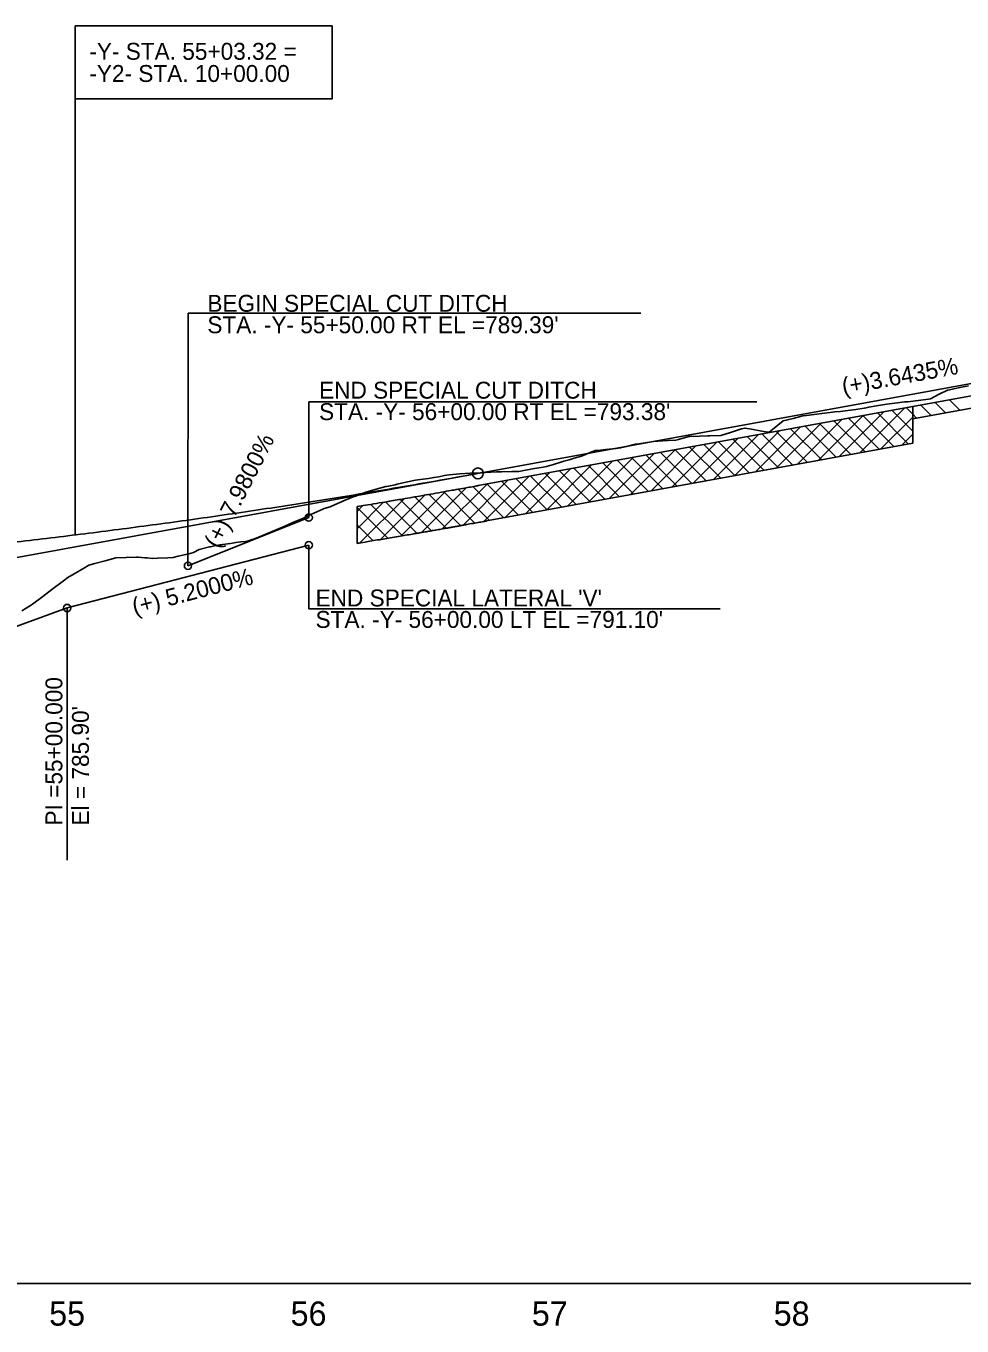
# Model space of a CAD drawing. Extents: x 579185 to 595036, y -53221 to -44640.
# Drawn here: x 583809 to 584197, y -47238 to -46700 of the extents above; entities that cross this region are included whole.
import ezdxf

# ---------------------------------------------------------------- set-up
doc = ezdxf.new("R2010")
doc.units = 0
for name, color, linetype in [('Exist Profile Cell', 7, 'Continuous'), ('Exist Vertical Profile Ground Line', 7, 'Continuous'), ('Exist Vertical Profile Horizontal Axis Label Major', 7, 'Continuous'), ('Prop Grid Mask', 7, 'Continuous'), ('Prop Hatching', 7, 'Continuous'), ('Prop Vertical Profile Curve Label', 7, 'Continuous'), ('Prop Vertical Profile Ditch Grade Left', 7, 'Continuous'), ('Prop Vertical Profile Ditch Grade Left Label', 7, 'Continuous'), ('Prop Vertical Profile Ditch Grade Right', 7, 'Continuous'), ('Prop Vertical Profile Ditch Grade Right Label', 7, 'Continuous'), ('Prop Vertical Profile Grade', 7, 'Continuous'), ('Prop Vertical Profile Grade Label', 7, 'Continuous'), ('Prop VPI Ditch Grade Left Label', 7, 'Continuous'), ('Prop VPI Ditch Grade Right Label', 7, 'Continuous'), ('Prop VPI Label', 7, 'Continuous'), ('Scratch_Level_1', 7, 'Continuous')]:
    doc.layers.add(name, color=color, linetype=linetype)

msp = doc.modelspace()

# ---------------------------------------------------------------- linework, layer by layer
at = {"layer": 'Exist Profile Cell'}
msp.add_line((579326.24, -47220.55), (584953.7, -47220.55), dxfattribs=at)
at = {"layer": 'Exist Vertical Profile Ground Line'}
for points in [[(584013.14, -46884.53), (584014.6, -46884.24), (584018.23, -46883.53), (584018.92, -46883.42), (584023.23, -46882.75), (584024.62, -46882.53), (584027.55, -46881.64), (584031.04, -46880.57), (584031.86, -46880.33), (584034.11, -46879.67), (584036.18, -46879.08), (584039.15, -46878.24), (584040.49, -46877.63), (584041.13, -46877.33), (584044.8, -46875.81), (584046.96, -46875.75), (584049.12, -46875.51), (584053.43, -46875.04), (584055.34, -46874.83), (584057.75, -46874.23), (584061.51, -46873.31), (584062.06, -46873.22), (584066.38, -46872.56), (584069.9, -46872.02), (584070.69, -46871.97), (584075, -46871.72), (584078.25, -46871.53), (584079.32, -46871.25), (584083.63, -46870.11), (584084, -46870.01), (584087.95, -46869.89), (584091.38, -46869.79), (584092.26, -46869.78), (584096.84, -46869.7), (584100.89, -46868.41), (584105.42, -46866.97), (584106.85, -46866.56), (584109.52, -46867.03), (584113.83, -46867.81), (584116.48, -46868.28), (584116.85, -46868.3), (584117.53, -46867.72), (584118.15, -46867.23), (584122.63, -46863.66), (584126.78, -46862.61), (584129.78, -46861.85), (584130.75, -46861.51), (584131.09, -46861.48), (584132.25, -46861.38), (584135.4, -46860.97), (584139.72, -46860.41), (584142.15, -46860.09), (584144.03, -46859.92), (584146.31, -46859.71), (584148.35, -46859.43), (584152.66, -46858.85), (584156.22, -46858.37), (584156.98, -46858.17), (584158.04, -46857.89), (584161.29, -46857.38), (584165.6, -46856.7), (584166.67, -46856.54), (584169.92, -46856.1), (584172.87, -46855.71), (584174.28, -46855.7), (584178.55, -46855.14), (584182.86, -46854.58), (584183.66, -46854.48), (584185.37, -46853.51), (584187.18, -46852.61), (584190.66, -46850.88), (584191.49, -46850.71), (584195.81, -46849.81), (584199.31, -46849.08)], [(583807.52, -46942.19), (583811, -46940.07), (583811.83, -46939.46), (583816.15, -46936.24), (583819.88, -46933.45), (583820.46, -46933.03), (583823.68, -46930.68), (583824.77, -46929.83), (583826.53, -46928.46), (583829.09, -46926.96), (583833.4, -46924.43), (583835.17, -46923.39), (583837.72, -46922.69), (583842.03, -46921.52), (583846.35, -46920.35), (583850.66, -46920.19), (583854.97, -46920.03), (583855.58, -46920.01), (583858.33, -46920.25), (583859.29, -46920.35), (583861.43, -46920.57), (583863.6, -46920.46), (583867.92, -46920.26), (583870.11, -46920.15), (583872.23, -46919.65), (583876.55, -46918.62), (583878.59, -46918.06), (583880.86, -46916.88), (583885.17, -46915.8), (583885.5, -46915.71), (583887.27, -46915.28), (583889.49, -46914.96), (583893.8, -46914.33), (583896.05, -46914), (583898.12, -46913.73), (583900.06, -46913.47), (583901.68, -46913.07), (583902.43, -46912.83), (583903.85, -46912.37), (583906.75, -46911.17), (583911.06, -46909.39), (583915.37, -46907.61), (583916.37, -46907.19), (583919.69, -46905.72), (583924, -46903.81), (583925.89, -46902.97), (583928.32, -46901.83), (583932.03, -46900.09), (583932.63, -46899.9), (583935.04, -46899.12), (583936.95, -46898.31), (583941.26, -46896.48), (583944.6, -46895.07), (583945.57, -46894.72), (583949.89, -46893.18), (583950.89, -46892.82), (583954.2, -46891.91), (583958.14, -46890.82), (583958.52, -46890.75), (583962.06, -46890.02), (583962.83, -46889.85), (583967.15, -46888.9), (583970.47, -46888.17), (583971.46, -46888.03), (583975.77, -46887.42), (583978.03, -46887.11), (583980.09, -46886.7), (583982.44, -46886.25), (583984.4, -46885.96), (583985.79, -46885.75), (583988.72, -46885.57), (583993.03, -46885.31), (583997.35, -46885.05), (584001.66, -46884.79), (584003.92, -46884.66), (584005.98, -46884.63), (584010.29, -46884.57), (584013.14, -46884.53)]]:
    msp.add_lwpolyline(points, dxfattribs=at)
at = {"layer": 'Prop Grid Mask'}
msp.add_lwpolyline([(583829.56, -46700.19), (583935.88, -46700.19), (583935.88, -46730.38), (583829.56, -46730.38)], close=True, dxfattribs=at)
at = {"layer": 'Prop Hatching'}
for p, q in [((583997.13, -46890.28), (584176.24, -46857.65)), ((584154.34, -46876.89), (584172.99, -46858.24)), ((584167.6, -46859.23), (584176.24, -46867.87)), ((584173.58, -46858.14), (584176.24, -46860.79)), ((584176.24, -46872.9), (584176.24, -46857.65)), ((584119.76, -46883.19), (584138.4, -46864.55)), ((584128.41, -46881.61), (584147.05, -46862.97)), ((584137.05, -46880.04), (584155.7, -46861.39)), ((584137.69, -46864.68), (584150.59, -46877.57)), ((584143.67, -46863.59), (584156.57, -46876.48)), ((584145.7, -46878.46), (584164.34, -46859.82)), ((584149.65, -46862.5), (584162.55, -46875.39)), ((584155.63, -46861.41), (584168.53, -46874.3)), ((584161.62, -46860.32), (584174.51, -46873.21)), ((584162.99, -46875.31), (584176.24, -46862.07)), ((584093.82, -46887.91), (584112.46, -46869.27)), ((584102.47, -46886.34), (584121.11, -46867.7)), ((584107.78, -46870.12), (584120.68, -46883.02)), ((584111.11, -46884.76), (584129.76, -46866.12)), ((584113.77, -46869.03), (584126.66, -46881.93)), ((584119.75, -46867.94), (584132.64, -46880.84)), ((584125.73, -46866.85), (584138.63, -46879.75)), ((584131.71, -46865.76), (584144.61, -46878.66)), ((584171.64, -46873.74), (584176.24, -46869.14)), ((583999.82, -46905.04), (584176.24, -46872.9)), ((584059.24, -46894.21), (584077.88, -46875.57)), ((584067.88, -46892.64), (584086.53, -46874)), ((584076.53, -46891.06), (584095.17, -46872.42)), ((584077.88, -46875.57), (584090.77, -46888.47)), ((584083.86, -46874.48), (584096.76, -46887.38)), ((584085.18, -46889.49), (584103.82, -46870.85)), ((584089.84, -46873.39), (584102.74, -46886.29)), ((584095.82, -46872.3), (584108.72, -46885.2)), ((584101.8, -46871.21), (584114.7, -46884.11)), ((584033.3, -46898.94), (584051.94, -46880.3)), ((584041.94, -46897.36), (584060.59, -46878.72)), ((584047.97, -46881.02), (584060.87, -46893.92)), ((584050.59, -46895.79), (584069.23, -46877.15)), ((584053.95, -46879.93), (584066.85, -46892.83)), ((584059.93, -46878.84), (584072.83, -46891.74)), ((584065.91, -46877.75), (584078.81, -46890.65)), ((584071.9, -46876.66), (584084.79, -46889.56)), ((584007.36, -46903.67), (584026, -46885.02)), ((584016.01, -46902.09), (584034.65, -46883.45)), ((584018.06, -46886.47), (584030.96, -46899.37)), ((584024.04, -46885.38), (584036.94, -46898.28)), ((584024.65, -46900.51), (584043.3, -46881.87)), ((584030.03, -46884.29), (584042.92, -46897.19)), ((584036.01, -46883.2), (584048.9, -46896.1)), ((584041.99, -46882.11), (584054.89, -46895.01)), ((583972.93, -46909.81), (583991.44, -46891.31)), ((583981.49, -46908.32), (584000.06, -46889.75)), ((583988.14, -46891.9), (584001.05, -46904.81)), ((583990.1, -46906.79), (584008.71, -46888.17)), ((583994.13, -46890.82), (584007.03, -46903.72)), ((583997.12, -46890.28), (583997.13, -46890.28)), ((583998.72, -46905.24), (584017.36, -46886.6)), ((584000.12, -46889.74), (584013.02, -46902.63)), ((584006.1, -46888.65), (584019, -46901.55)), ((584012.08, -46887.56), (584024.98, -46900.46)), ((583946.24, -46908.22), (583957.18, -46897.28)), ((583947.43, -46914.1), (583965.69, -46895.83)), ((583955.9, -46912.7), (583974.24, -46894.36)), ((583958.02, -46897.14), (583971.02, -46910.14)), ((583964.07, -46896.11), (583977.05, -46909.1)), ((583964.4, -46911.27), (583982.81, -46892.85)), ((583970.1, -46895.08), (583983.07, -46908.04)), ((583976.13, -46894.03), (583989.07, -46906.97)), ((583982.14, -46892.97), (583995.06, -46905.89)), ((583946.24, -46901.15), (583948.69, -46898.69)), ((583946.24, -46914.3), (583946.24, -46899.1)), ((583946.24, -46899.5), (583958.93, -46912.19)), ((583951.96, -46898.15), (583964.98, -46911.17)), ((583946.24, -46906.57), (583952.87, -46913.2)), ((583999.77, -46905.05), (583999.82, -46905.04)), ((583946.24, -46913.64), (583946.8, -46914.2))]:
    msp.add_line(p, q, dxfattribs=at)
for points in [[(583946.24, -46899.1), (583947.7, -46898.85), (583949.17, -46898.61), (583954.54, -46897.72), (583958.45, -46897.07), (583965.58, -46895.86), (583968.8, -46895.3), (583975.25, -46894.19), (583978.47, -46893.63), (583983.86, -46892.67), (583986, -46892.28), (583990.3, -46891.51), (583992.45, -46891.12), (583995.44, -46890.59), (583996.28, -46890.43), (583997.12, -46890.28)], [(583946.24, -46914.3), (583947.5, -46914.09), (583948.76, -46913.88), (583955.7, -46912.74), (583961.37, -46911.79), (583968.55, -46910.56), (583970.05, -46910.31), (583972.31, -46909.92), (583973.06, -46909.79), (583974.57, -46909.53), (583975.33, -46909.4), (583977.61, -46909), (583979.13, -46908.74), (583981.92, -46908.25), (583983.18, -46908.03), (583984.84, -46907.73), (583985.24, -46907.66), (583985.92, -46907.54), (583986.19, -46907.49), (583986.75, -46907.39), (583987.03, -46907.34), (583987.87, -46907.19), (583988.43, -46907.09), (583990.11, -46906.78), (583991.23, -46906.58), (583994.58, -46905.98), (583996.82, -46905.58), (583999.3, -46905.13), (583999.53, -46905.09), (583999.77, -46905.05)]]:
    msp.add_open_spline(points, degree=3, dxfattribs=at)
at = {"layer": 'Prop Vertical Profile Curve Label'}
msp.add_line((583829.56, -46910.8), (583829.56, -46730.38), dxfattribs=at)
msp.add_circle((583996.24, -46885.36), 2.25, dxfattribs=at)
at = {"layer": 'Prop Vertical Profile Ditch Grade Left'}
msp.add_lwpolyline([(583521.24, -47013.6), (583626.24, -47002.05), (583726.24, -46977.55), (583826.24, -46941.05), (583926.24, -46915.05)], dxfattribs=at)
at = {"layer": 'Prop Vertical Profile Ditch Grade Left Label'}
for p, q in [((583926.24, -46941.35), (583926.24, -46915.05)), ((583826.24, -47045.34), (583826.24, -46941.05)), ((583926.24, -46941.35), (584096.51, -46941.35))]:
    msp.add_line(p, q, dxfattribs=at)
for centre in [(583926.24, -46915.05), (583826.24, -46941.05)]:
    msp.add_circle(centre, 1.5, dxfattribs=at)
at = {"layer": 'Prop Vertical Profile Ditch Grade Right'}
msp.add_line((583876.24, -46923.6), (583926.24, -46903.65), dxfattribs=at)
at = {"layer": 'Prop Vertical Profile Ditch Grade Right Label'}
for p, q in [((583876.33, -46819.04), (583876.24, -46923.6)), ((583876.33, -46819.04), (584063.66, -46819.04)), ((583926.28, -46855.75), (583926.24, -46903.65)), ((583926.28, -46855.75), (584111.69, -46855.75))]:
    msp.add_line(p, q, dxfattribs=at)
at = {"layer": 'Prop Vertical Profile Grade'}
msp.add_line((583996.24, -46885.36), (584356.24, -46819.78), dxfattribs=at)
msp.add_spline([(583296.24, -46926.07), (583310.24, -46926.95), (583324.24, -46927.77), (583338.24, -46928.52), (583352.24, -46929.2), (583366.24, -46929.81), (583380.24, -46930.35), (583394.24, -46930.82), (583408.24, -46931.22), (583422.24, -46931.55), (583436.24, -46931.82), (583450.24, -46932.01), (583464.24, -46932.13), (583478.24, -46932.19), (583492.24, -46932.17), (583506.24, -46932.09), (583520.24, -46931.93), (583534.24, -46931.71), (583548.24, -46931.42), (583562.24, -46931.05), (583576.24, -46930.62), (583590.24, -46930.12), (583604.24, -46929.55), (583618.24, -46928.91), (583632.24, -46928.2), (583646.24, -46927.42), (583660.24, -46926.57), (583674.24, -46925.65), (583688.24, -46924.66), (583702.24, -46923.61), (583716.24, -46922.48), (583730.24, -46921.28), (583744.24, -46920.02), (583758.24, -46918.68), (583772.24, -46917.28), (583786.24, -46915.81), (583800.24, -46914.26), (583814.24, -46912.65), (583828.24, -46910.97), (583842.24, -46909.22), (583856.24, -46907.39), (583870.24, -46905.5), (583884.24, -46903.54), (583898.24, -46901.51), (583912.24, -46899.41), (583926.24, -46897.25), (583940.24, -46895.01), (583954.24, -46892.7), (583968.24, -46890.32), (583982.24, -46887.88), (583996.24, -46885.36)], degree=3, dxfattribs=at)
at = {"layer": 'Prop VPI Ditch Grade Right Label'}
for centre in [(583926.24, -46903.65), (583876.24, -46923.6)]:
    msp.add_circle(centre, 1.5, dxfattribs=at)
at = {"layer": 'Prop VPI Label'}
msp.add_line((583996.24, -46885.36), (583648.94, -46948.63), dxfattribs=at)
at = {"layer": 'Scratch_Level_1'}
for p, q in [((584176.24, -46857.65), (584357.13, -46824.7)), ((584176.24, -46862.74), (584358.03, -46829.62)), ((584176.24, -46857.65), (584176.24, -46862.74)), ((584179.56, -46857.05), (584183.86, -46861.35)), ((584185.54, -46855.96), (584189.84, -46860.26)), ((584191.52, -46854.87), (584195.82, -46859.17)), ((584176.24, -46860.79), (584177.88, -46862.44))]:
    msp.add_line(p, q, dxfattribs=at)

# ---------------------------------------------------------------- texts
at = {"layer": 'Exist Vertical Profile Horizontal Axis Label Major'}
for s, p in [('55', (583818.78, -47238.05)), ('56', (583918.72, -47238.05)), ('57', (584018.58, -47238.05)), ('58', (584118.7, -47238.05))]:
    msp.add_text(s, height=10, dxfattribs=at).set_placement(p)
at = {"layer": 'Prop Vertical Profile Ditch Grade Left Label'}
msp.add_text('(+) 5.2000%', height=7, rotation=14.5742, dxfattribs=at).set_placement((583854.15, -46944))
for s, p in [("END SPECIAL LATERAL 'V'", (583929.06, -46940.41)), ("STA. -Y- 56+00.00 LT EL =791.10'", (583929.06, -46949.29))]:
    msp.add_text(s, height=7, dxfattribs=at).set_placement(p)
at = {"layer": 'Prop Vertical Profile Ditch Grade Right'}
for s, p in [('END SPECIAL CUT DITCH', (583930.52, -46854.41)), ("STA. -Y- 56+00.00 RT EL =793.38'", (583930.52, -46863.29))]:
    msp.add_text(s, height=7, dxfattribs=at).set_placement(p)
at = {"layer": 'Prop Vertical Profile Ditch Grade Right Label'}
for s, p in [('BEGIN SPECIAL CUT DITCH', (583884.26, -46818.46)), ("STA. -Y- 55+50.00 RT EL =789.39'", (583884.26, -46827.34))]:
    msp.add_text(s, height=7, dxfattribs=at).set_placement(p)
msp.add_text('(+) 7.9800%', height=7, rotation=62.8827, dxfattribs=at).set_placement((583888.89, -46916.8))
at = {"layer": 'Prop Vertical Profile Grade Label'}
msp.add_text('(+)3.6435%', height=7, rotation=10.3247, dxfattribs=at).set_placement((584147.62, -46852.84))
at = {"layer": 'Prop VPI Ditch Grade Left Label'}
for s, p in [('PI =55+00.000', (583824.24, -47031.05)), ("El = 785.90'", (583835.24, -47031.05))]:
    msp.add_text(s, height=7, rotation=90, dxfattribs=at).set_placement(p)
at = {"layer": 'Prop VPI Label'}
for s, p in [('-Y- STA. 55+03.32 =', (583835.4, -46714.17)), ('-Y2- STA. 10+00.00', (583835.4, -46723.35))]:
    msp.add_text(s, height=7, dxfattribs=at).set_placement(p)

doc.saveas('drawing.dxf')
